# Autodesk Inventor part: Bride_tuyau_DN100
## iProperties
Shininess: 64.0
Length Units: 11269
Angle Units: 11279
Time Units: 11290
Mass Units: 11283
Length Display Precision: 3
Angle Display Precision: 2
Compacted: True
Part Number: Bride_tuyau_DN100
Document SubType Name: Modeling
Created: 2008-02
Material: Par défaut
Designer: Pascal
Density: 0.0
Volumn: 0.0
Area: 0.0
PropertySet Name: Model Information
Control State: 0
Master: False
Checked Out: False
MATIERE_PIECE: X2CrNi 18-11
OBSERVATIONS: ep. 8
DESIGNATION: Bride DN 100
Author: Pascal
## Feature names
1. Extrusion1
2. Extrusion2
3. Réseau circulaire1 [Circular Pattern]
